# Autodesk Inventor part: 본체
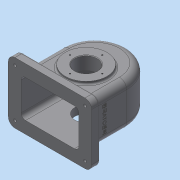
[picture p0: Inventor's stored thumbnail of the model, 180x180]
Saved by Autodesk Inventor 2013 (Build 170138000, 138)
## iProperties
Created: 2016-10
Part Number: 본체
Material: 일반
Document SubType Name: Modeling
Designer: dgall
Density: 1 g/cm^3
Author: dgall
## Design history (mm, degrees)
sketch "스케치1" dims "d0" = 116
  geometry: L1 (-58, -80)-(58, -80); L2 (58, -80)-(58, 0); L3 (58, 0)-(-58, 0); L4 (-58, 0)-(-58, -80); 2 further points
  constraints: 8 end point, 2 parallel, 2 vertical, 1 coincident, 1 horizontal, 1 horizontal alignment, 1 perpendicular, 2 other
  dimensions: "d3" = 80 distance from line of L1 point (0, 0)
extrude "돌출1" new body sketch "스케치1" stored distance "d4" = 77; taper "d5" = 0 deg
sketch "스케치13"
  geometry: L1 (58, 0)-(58, -80) reference; L2 (58, -80)-(-58, -80) reference; L3 (-58, -80)-(-58, 0) reference; L4 (52, -80)-(52, 0); L5 (-52, 0)-(-52, -80); L6 (-52, -80)-(52, -80); A1 r 58 centre (0, 0) between (58, 0) and (-58, 0) reference; A2 r 52 centre (0, 0) between (52, 0) and (-52, 0); 1 further point
  constraints: 6 end point, 2 point on circle, 1 centre point, 1 perpendicular, 1 point on line, 2 other
  dimensions: "d126" = 6 distance between parallel lines of L1 L4
extrude "돌출8" cut sketch "스케치13" stored distance "d127" = 67; taper "d128" = 0 deg
fillet "모깎기1" dims "d25" = 13
sketch "스케치2"
  geometry: L1 (-58, -80)-(58, -80) reference; C1 r 37.5 at (0, -15); A1 r 58 centre (0, 0) between (58, 0) and (-58, 0) reference
  constraints: 1 centre point, 1 vertical alignment
  dimensions: "d7" = 65 distance from line of L1 C1.centre; "d8" = 75 diameter of C1
extrude "돌출2" join sketch "스케치2" distance "d9" = 5; taper "d10" = 0 deg
sketch "스케치3"
  geometry: L1 (-58, -80)-(58, -80) reference; C1 r 31 at (0, -15); A1 r 58 centre (0, 0) between (58, 0) and (-58, 0) reference
  constraints: 1 centre point, 1 vertical alignment
  dimensions: "d11" = 65 distance from line of L1 C1.centre; "d12" = 62 diameter of C1
extrude "돌출3" join sketch "스케치3" distance "d13" = 10; taper "d14" = 0 deg
node "작업 평면1"
sketch "스케치4"
  geometry: L1 (52, -65)-(-52, -65) reference; C1 r 28 at (0, 0); 1 further point
  constraints: 1 centre point, 1 vertical alignment
  dimensions: "d16" = 56 diameter of C1; "d129" = 65 distance from line of L1 C1.centre
extrude "돌출4" join sketch "스케치4" stored distance "d19" = 10; taper "d20" = 40 deg
sketch "스케치5"
  geometry: C1 r 31 at (0, 0) reference; C2 r 20 at (0, 0); 1 further point
  constraints: 1 centre point, 1 coincident
  dimensions: "d21" = 40 diameter of C2
extrude "돌출5" cut sketch "스케치5" stored distance "d23" = 10; taper "d24" = 0 deg
fillet "모깎기5" dims "d130" = 8
sketch "스케치7"
  geometry: L1 (98, -13)-(98, -64) reference; L2 (90, -72)-(0, -72) reference; L3 (-8, -64)-(-8, -13) reference; L4 (0, -5)-(90, -5) reference; L5 (0, 0)-(90, 0) reference; L6 (90, -77)-(0, -77) reference; L7 (103, -64)-(103, -13) reference; L8 (108, -93.5)-(-18, -93.5); L9 (-30, -81.5)-(-30, 4.5); L10 (-18, 16.5)-(108, 16.5); L11 (120, 4.5)-(120, -81.5); L12 (120, -93.5)-(-30, 16.5); L13 (-30, -93.5)-(120, 16.5); A1 r 8 centre (90, -13) between (98, -13) and (90, -5) reference; A2 r 8 centre (90, -64) between (90, -72) and (98, -64) reference; A3 r 8 centre (0, -64) between (-8, -64) and (0, -72) reference; A4 r 8 centre (0, -13) between (0, -5) and (-8, -13) reference; A5 r 13 centre (90, -13) between (103, -13) and (90, 0) reference; A6 r 13 centre (0, -64) between (-13, -64) and (0, -77) reference; A7 r 13 centre (90, -64) between (90, -77) and (103, -64) reference; A8 r 12 centre (-18, 4.5) between (-18, 16.5) and (-30, 4.5); A9 r 12 centre (108, 4.5) between (120, 4.5) and (108, 16.5); A10 r 12 centre (108, -81.5) between (108, -93.5) and (120, -81.5); A11 r 12 centre (-18, -81.5) between (-30, -81.5) and (-18, -93.5); 1 further point
  constraints: 12 end point, 8 point on circle, 8 point on line, 8 tangent, 4 centre point, 3 equal radius, 2 midpoint, 2 parallel, 1 horizontal, 1 perpendicular
  dimensions: "d31" = 150 distance of L12.end L13.end; "d33" = 110 distance of L13.start L12.end; "d34" = 12 radius of A8
extrude "돌출6" join sketch "스케치7" distance "d35" = 15; taper "d36" = 0 deg
node "작업 평면3"
sketch "스케치8"
  geometry: C1 r 6 at (63, 55); 1 further point
  constraints: 1 centre point, 1 coincident
  dimensions: "d76" = 12 diameter of C1
extrude "돌출7" join sketch "스케치8" stored distance "d78" = 15; taper "d79" = 10 deg
sketch "스케치9"
  geometry: L1 (108, 81.5)-(-18, 81.5); L2 (-18, 81.5)-(-18, -4.5); L3 (-18, -4.5)-(108, -4.5); L4 (108, -4.5)-(108, 81.5); A1 r 12 centre (-18, -4.5) between (-30, -4.5) and (-18, -16.5) reference; A2 r 12 centre (108, 81.5) between (120, 81.5) and (108, 93.5) reference; A3 r 12 centre (-18, 81.5) between (-18, 93.5) and (-30, 81.5) reference; 1 further point
  constraints: 8 end point, 2 parallel, 1 horizontal, 1 perpendicular
hole "구멍5" sketch "스케치9" at (108, -4.5), (-18, -4.5), (108, 81.5), (-18, 81.5) diameter "d80" = 5; stored, may be unused: countersink angle "d84" = 90 deg, drill point angle "d86" = 118 deg; dims "d81" = 6, "d82" = 12, "d83" = 5, "d85" = 8
hole "구멍6" diameter "d89" = 4.459; stored, may be unused: countersink angle "d93" = 90 deg, drill point angle "d95" = 118 deg; dims "d87" = 10, "d88" = 10, "d90" = 6, "d91" = 12, "d92" = 5, "d94" = 8
sketch "스케치10"
  geometry: C1 r 20 at (0, 0) reference; 2 further points
  constraints: 1 vertical alignment
  dimensions: "d96" = 29 distance of C1.centre point (0, 29)
hole "구멍7" sketch "스케치10" at (0, 29) diameter "d97" = 2.459; stored, may be unused: countersink angle "d101" = 90 deg, drill point angle "d103" = 118 deg; dims "d98" = 6, "d99" = 12, "d100" = 5, "d102" = 8
sketch "스케치11"
  geometry: C1 r 20 at (0, 0) reference; 2 further points
  constraints: 1 vertical alignment
  dimensions: "d104" = 26 distance of C1.centre point (0, 26)
hole "구멍8" sketch "스케치11" at (0, 26) diameter "d105" = 2.459; stored, may be unused: countersink angle "d109" = 90 deg, drill point angle "d111" = 118 deg; dims "d106" = 6, "d107" = 12, "d108" = 5, "d110" = 8
sketch "스케치12"
  geometry: L1 (86, 0)-(0, 0) reference; L2 (4.5, 80)-(4.5, 15) reference; 2 further points
  constraints: 1 other
  dimensions: "d118" = 38.5 distance from line of point (43, 40) L2; "d119" = 40 distance from line of point (43, 40) L1
feature "엠보싱1" sketch "스케치12" dims "d0" = 116, "d3" = 80, "d11" = 65, "d12" = 62, "d120" = 0.5, "d121" = 0
fillet "모깎기4" dims "d122" = 3
chamfer "모따기1" distance "d123" = 1; stored, may be unused: second distance "d124" = 2, angle "d125" = 45 deg
node "솔리드1"
pattern_circular "원형 패턴1" dims angle "d113" = 360 deg
pattern_circular "원형 패턴2" dims angle "d116" = 360 deg
node "절단 모서리 투영1"
other parameters: "d15" = -24, "d75" = -144
